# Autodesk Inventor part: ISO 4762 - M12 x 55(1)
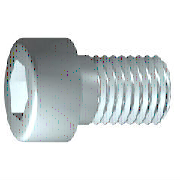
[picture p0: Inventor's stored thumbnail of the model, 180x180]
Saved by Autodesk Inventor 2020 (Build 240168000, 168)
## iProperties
Created: 2019-01
Part Number: ISO 4762 - M12 x 55(1)
Material: Nerezová ocel 440C
Description: Šroub s válcovou hlavou s vnitřním šestihranem
Document SubType Name: Modeling
Standard: ISO 4762
Designer: doma
Standard Revision: Fourth edition 2004-03-01
Standards Organization: ISO
Language: cs-CZ
Size Designation: M12 x 55
Categories: <MemberInstance><Categories><Category DisplayName="Spojovací materiál" InternalName="e4da775c-781d-43d5-af7c-5136215cf5a6" Mnemonic="FSTN"><Category DisplayName
Density: 7.75 g/cm^3
Appearance: Pololeštěná
IsCustomPart: 0
Author: doma
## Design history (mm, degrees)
sketch "Náčrt1"
  geometry: L1 (-2.667, 0)-(55, 0); L2 (55, 0)-(55, 6); L3 (55, 6)-(19, 6); L4 (19, 6)-(17.926, 6); L5 (17.926, 6)-(0, 6); L6 (0, 6)-(0, 9); L7 (0, 9)-(-12, 9); L8 (-12, 9)-(-12, 5.774); L9 (-12, 5.774)-(-6, 5.774); L10 (-6, 5.774)-(-2.667, 0); L11 (-25.4, 0)-(68.4, 0) reference; L12 (0, -1.8)-(0, 10.8) reference; L13 (19, 6)-(0, 6)
  constraints: 22 end point, 6 parallel, 2 collinear, 2 perpendicular, 1 horizontal, 1 point on line
  dimensions: "d1" = 36 distance from line of L3.end L2 (= GEL); "d2" = 1.07364 distance of L4.end L3.end (computed from GAL); "d3" = 12 distance between parallel lines of L8 L6 (= KOH); "d4" = 6 distance of L8.end L9.end (= INTI); "d5" = 60 deg angle of L10 L1; "d6" = 12 diameter of L3 L1 (= GD); "d7" = 12 diameter of L5 L1 (= BDM); "d8" = 11.54701 diameter of L9 L1 (= 1.1547 x SW); "d9" = 18 diameter of L7 L1 (= KOD); "d26" = 55 distance between parallel lines of L12 L2 (= NLG)
revolve "Těleso" sketch "Náčrt1" stored, may be unused: angle "d10" = 90 deg
sketch "Náčrt2"
  geometry: L1 (0, -12.6)-(0, 12.6) reference; L2 (-12.6, 0)-(12.6, 0) reference; L3 (5.774, 0)-(2.887, -5); L4 (2.887, -5)-(-2.887, -5); L5 (-2.887, -5)-(-5.774, 0); L6 (-5.774, 0)-(-2.887, 5); L7 (-2.887, 5)-(2.887, 5); L8 (2.887, 5)-(5.774, 0); 2 further points
  constraints: 12 end point, 1 coincident, 1 horizontal alignment, 1 point on line, 12 other
extrude "Drážka" join sketch "Náčrt2" stored distance "d11" = 10; taper "d12" = 0 deg
workplane "Work Plane1"
fillet "Fillet2" dims "d30" = 0.1 (= R)
body "Solid1"
fillet "Zaoblení1" dims "d17" = 1.2 (= RR)
feature "Závit" dims "d13" = 36 (= GEL), "d14" = 0
chamfer "Zkosení1" distance "d15" = 1.07354 (= -0.5 x SPD + 0.5 x GD); stored, may be unused: second distance "d16" = 1.07354 (= GUL), angle "d27" = 45 deg
other parameters: "GD" = 12 [user parameter; used in 2 equation terms], "NLG" = 55 [user parameter; used in 1 equation term], "GEL" = 36 [user parameter; used in 2 equation terms], "KOD" = 18 [user parameter; used in 1 equation term], "KOH" = 12 [user parameter; used in 1 equation term], "INTI" = 6 [user parameter; used in 1 equation term], "GAL" = 1.07354 (= 0.61345 x PTC) [user parameter; used in 1 equation term], "GUL" = 1.07354 (= 0.61345 x PTC) [user parameter; used in 1 equation term], "BDM" = 12 (= NND) [user parameter; used in 1 equation term], "RR" = 1.2 [user parameter; used in 1 equation term], "SPD" = 9.85293 (= NND - 1.2269 x PTC) [user parameter; used in 1 equation term], "d19" = 0, "d28" = 0, "d29" = 0, "R" = 0.1 [user parameter; used in 1 equation term], "TOA" = 30 deg [user parameter], "GD1" = 9.85293 (= THREADDIA - 1.2269 x PTC) [user parameter], "THREADDIA" = 12 [user parameter; used in 1 equation term], "FAWI" = 45 deg [user parameter], "TPU" = 5.71429 (computed from PTC) [user parameter], "PTC" = 1.75 [user parameter; used in 5 equation terms], "NND" = 12 [user parameter; used in 2 equation terms], "E0" = 11.55 (= 1.155 x SW) [user parameter]
